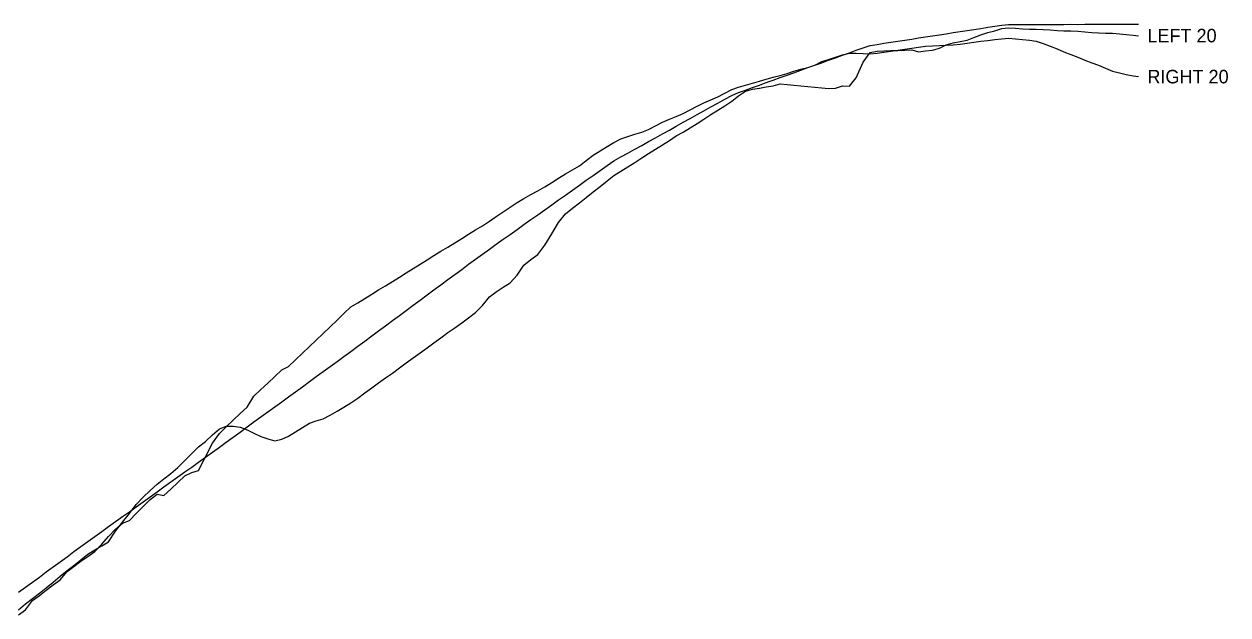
# Model space of a CAD drawing. Extents: x 2005261 to 2010661, y 1001568 to 1006764.
# Drawn here: x 2008591 to 2009460, y 1004765 to 1005191 of the extents above; entities that cross this region are included whole.
import ezdxf

# ---------------------------------------------------------------- set-up
doc = ezdxf.new("R2010")
doc.units = 0
for name, color, linetype in [('RD_DDB_Profile_EX', 7, 'Continuous'), ('RD_Sketch2', 7, 'Continuous'), ('RD_Sketch3', 7, 'Continuous')]:
    doc.layers.add(name, color=color, linetype=linetype)

msp = doc.modelspace()

# ---------------------------------------------------------------- linework, layer by layer
at = {"layer": 'RD_DDB_Profile_EX'}
for points in [[(2009176.73, 1005166.94), (2009181.73, 1005168.71), (2009186.73, 1005170.5), (2009191.73, 1005172.29), (2009196.73, 1005174.08), (2009201.73, 1005175.83), (2009206.73, 1005176.59), (2009211.73, 1005177.35), (2009216.73, 1005178.12), (2009221.73, 1005178.89), (2009226.73, 1005179.66), (2009231.73, 1005180.42), (2009236.73, 1005181.19), (2009241.73, 1005181.96), (2009246.73, 1005182.73), (2009251.73, 1005183.5), (2009256.73, 1005184.26), (2009261.73, 1005185.03), (2009266.73, 1005185.8), (2009271.73, 1005186.57), (2009276.73, 1005187.34), (2009281.73, 1005188.11), (2009286.73, 1005188.87), (2009291.73, 1005189.64), (2009296.73, 1005190.41), (2009301.73, 1005190.94), (2009306.73, 1005190.95), (2009311.73, 1005190.97), (2009316.73, 1005190.98), (2009321.73, 1005191), (2009326.73, 1005190.96), (2009331.73, 1005190.98), (2009336.73, 1005191), (2009341.73, 1005191.02), (2009346.73, 1005191.04), (2009351.73, 1005191.02), (2009356.73, 1005191.04), (2009361.73, 1005191.06), (2009366.73, 1005191.09), (2009371.73, 1005191.11), (2009376.73, 1005191.11), (2009381.73, 1005191.14), (2009386.73, 1005191.17), (2009391.73, 1005191.19), (2009395.62, 1005191.21)], [(2008676.73, 1004846.43), (2008681.73, 1004850.01), (2008686.73, 1004853.59), (2008691.73, 1004857.17), (2008696.73, 1004860.76), (2008701.73, 1004864.34), (2008706.73, 1004867.92), (2008711.73, 1004871.5), (2008716.73, 1004875.08), (2008721.73, 1004878.67), (2008726.73, 1004882.25), (2008731.73, 1004885.83), (2008736.73, 1004889.47), (2008741.73, 1004893.11), (2008746.73, 1004896.75), (2008751.73, 1004900.4), (2008756.73, 1004904.02), (2008761.73, 1004907.66), (2008766.73, 1004911.31), (2008771.73, 1004914.95), (2008776.73, 1004918.59), (2008781.73, 1004922.22), (2008786.73, 1004925.86), (2008791.73, 1004929.5), (2008796.73, 1004933.14), (2008801.73, 1004936.79), (2008806.73, 1004940.42), (2008811.73, 1004944.06), (2008816.73, 1004947.7), (2008821.73, 1004951.35), (2008826.73, 1004955.01), (2008831.73, 1004958.71), (2008836.73, 1004962.41), (2008841.73, 1004966.11), (2008846.73, 1004969.81), (2008851.73, 1004973.5), (2008856.73, 1004977.2), (2008861.73, 1004980.9), (2008866.73, 1004984.6), (2008871.73, 1004988.3), (2008876.73, 1004991.99), (2008881.73, 1004995.69), (2008886.73, 1004999.39), (2008891.73, 1005003.09), (2008896.73, 1005006.79), (2008901.73, 1005010.48), (2008906.73, 1005014.18), (2008911.73, 1005017.88), (2008916.73, 1005021.58), (2008921.73, 1005025.24), (2008926.73, 1005028.79), (2008931.73, 1005032.33), (2008936.73, 1005035.88), (2008941.73, 1005039.42), (2008946.73, 1005042.98), (2008951.73, 1005046.53), (2008956.73, 1005050.07), (2008961.73, 1005053.62), (2008966.73, 1005057.16), (2008971.73, 1005060.72), (2008976.73, 1005064.27), (2008981.73, 1005067.82), (2008986.73, 1005071.36), (2008991.73, 1005074.91), (2008996.73, 1005078.47), (2009001.73, 1005082.01), (2009006.73, 1005085.56), (2009011.73, 1005089.11), (2009016.73, 1005092.53), (2009021.73, 1005095.31), (2009026.73, 1005098.08), (2009031.73, 1005100.86), (2009036.73, 1005103.64), (2009041.73, 1005106.42), (2009046.73, 1005109.19), (2009051.73, 1005111.97), (2009056.73, 1005114.74), (2009061.73, 1005117.52), (2009066.73, 1005120.3), (2009071.73, 1005123.07), (2009076.73, 1005125.85), (2009081.73, 1005128.62), (2009086.73, 1005131.38), (2009091.73, 1005134.15), (2009096.73, 1005136.91), (2009101.73, 1005139.68), (2009106.73, 1005141.79), (2009111.73, 1005143.58), (2009116.73, 1005145.37), (2009121.73, 1005147.16), (2009126.73, 1005148.95), (2009131.73, 1005150.77), (2009136.73, 1005152.56), (2009141.73, 1005154.35), (2009146.73, 1005156.14), (2009151.73, 1005157.93), (2009156.73, 1005159.76), (2009161.73, 1005161.56), (2009166.73, 1005163.35), (2009171.73, 1005165.14), (2009176.73, 1005166.94)], [(2008586.73, 1004781.12), (2008591.73, 1004784.79), (2008596.73, 1004788.46), (2008601.73, 1004792.12), (2008606.73, 1004795.79), (2008611.73, 1004799.45), (2008616.73, 1004803.12), (2008621.73, 1004806.79), (2008626.73, 1004810.45), (2008631.73, 1004814.12), (2008636.73, 1004817.77), (2008641.73, 1004821.35), (2008646.73, 1004824.93), (2008651.73, 1004828.52), (2008656.73, 1004832.1), (2008661.73, 1004835.68), (2008666.73, 1004839.26), (2008671.73, 1004842.85), (2008676.73, 1004846.43)]]:
    msp.add_lwpolyline(points, dxfattribs=at)
at = {"layer": 'RD_Sketch2'}
for points in [[(2009176.73, 1005144.91), (2009181.73, 1005146.75), (2009186.73, 1005146.31), (2009191.73, 1005152.42), (2009196.73, 1005163.73), (2009201.73, 1005170.8), (2009206.73, 1005171.76), (2009211.73, 1005171.92), (2009216.73, 1005172.09), (2009221.73, 1005172.26), (2009226.73, 1005172.43), (2009231.73, 1005172.6), (2009236.73, 1005171.19), (2009241.73, 1005171.82), (2009246.73, 1005172.45), (2009251.73, 1005173.85), (2009256.73, 1005176.14), (2009261.73, 1005177.59), (2009266.73, 1005178.64), (2009271.73, 1005179.69), (2009276.73, 1005181.42), (2009281.73, 1005183.51), (2009286.73, 1005185.02), (2009291.73, 1005186.24), (2009296.73, 1005188.11), (2009301.73, 1005188.53), (2009306.73, 1005188.19), (2009311.73, 1005187.86), (2009316.73, 1005187.6), (2009321.73, 1005187.66), (2009326.73, 1005187.42), (2009331.73, 1005187.05), (2009336.73, 1005186.68), (2009341.73, 1005186.31), (2009346.73, 1005186.3), (2009351.73, 1005186.03), (2009356.73, 1005185.63), (2009361.73, 1005185.22), (2009366.73, 1005184.82), (2009371.73, 1005184.62), (2009376.73, 1005184.63), (2009381.73, 1005184.15), (2009386.73, 1005183.66), (2009391.73, 1005183.18), (2009395.62, 1005182.81)], [(2008676.73, 1004849.84), (2008681.73, 1004854.53), (2008686.73, 1004859.23), (2008691.73, 1004863.07), (2008696.73, 1004866.77), (2008701.73, 1004871.28), (2008706.73, 1004876.21), (2008711.73, 1004881.15), (2008716.73, 1004886.09), (2008721.73, 1004889.97), (2008726.73, 1004894.77), (2008731.73, 1004899.11), (2008736.73, 1004900.95), (2008741.73, 1004901.09), (2008746.73, 1004900.16), (2008751.73, 1004898.35), (2008756.73, 1004895.93), (2008761.73, 1004893.63), (2008766.73, 1004891.74), (2008771.73, 1004890.52), (2008776.73, 1004891.62), (2008781.73, 1004893.83), (2008786.73, 1004896.91), (2008791.73, 1004899.99), (2008796.73, 1004903.06), (2008801.73, 1004904.83), (2008806.73, 1004906.38), (2008811.73, 1004908.89), (2008816.73, 1004911.79), (2008821.73, 1004914.7), (2008826.73, 1004917.82), (2008831.73, 1004921.29), (2008836.73, 1004924.97), (2008841.73, 1004928.65), (2008846.73, 1004932.33), (2008851.73, 1004935.9), (2008856.73, 1004939.36), (2008861.73, 1004943.05), (2008866.73, 1004946.73), (2008871.73, 1004950.41), (2008876.73, 1004953.98), (2008881.73, 1004957.43), (2008886.73, 1004961.12), (2008891.73, 1004964.81), (2008896.73, 1004968.5), (2008901.73, 1004972.06), (2008906.73, 1004975.54), (2008911.73, 1004979.24), (2008916.73, 1004982.93), (2008921.73, 1004987.98), (2008926.73, 1004994.46), (2008931.73, 1004998.02), (2008936.73, 1005001.26), (2008941.73, 1005004.49), (2008946.73, 1005009.9), (2008951.73, 1005017.29), (2008956.73, 1005021.28), (2008961.73, 1005024.99), (2008966.73, 1005031.75), (2008971.73, 1005039.86), (2008976.73, 1005047.96), (2008981.73, 1005054.3), (2008986.73, 1005058.25), (2008991.73, 1005062.19), (2008996.73, 1005066.14), (2009001.73, 1005070.09), (2009006.73, 1005074.03), (2009011.73, 1005077.98), (2009016.73, 1005081.85), (2009021.73, 1005085.03), (2009026.73, 1005088.21), (2009031.73, 1005091.39), (2009036.73, 1005094.57), (2009041.73, 1005097.76), (2009046.73, 1005100.94), (2009051.73, 1005104.12), (2009056.73, 1005107.3), (2009061.73, 1005110.48), (2009066.73, 1005113.23), (2009071.73, 1005116.31), (2009076.73, 1005119.5), (2009081.73, 1005122.7), (2009086.73, 1005125.9), (2009091.73, 1005129.09), (2009096.73, 1005132.29), (2009101.73, 1005135.49), (2009106.73, 1005139.41), (2009111.73, 1005142.86), (2009116.73, 1005144.19), (2009121.73, 1005145.03), (2009126.73, 1005145.87), (2009131.73, 1005146.71), (2009136.73, 1005147.99), (2009141.73, 1005147.53), (2009146.73, 1005147.07), (2009151.73, 1005146.61), (2009156.73, 1005146.14), (2009161.73, 1005145.68), (2009166.73, 1005145.22), (2009171.73, 1005144.76), (2009176.73, 1005144.91)], [(2008586.73, 1004768.38), (2008591.73, 1004772.7), (2008596.73, 1004776.66), (2008601.73, 1004780.48), (2008606.73, 1004784.3), (2008611.73, 1004788.49), (2008616.73, 1004792.79), (2008621.73, 1004796.73), (2008626.73, 1004800.55), (2008631.73, 1004804.64), (2008636.73, 1004808.7), (2008641.73, 1004811.66), (2008646.73, 1004814.62), (2008651.73, 1004817.57), (2008656.73, 1004825.24), (2008661.73, 1004831.66), (2008666.73, 1004838.08), (2008671.73, 1004844.51), (2008676.73, 1004849.84)]]:
    msp.add_lwpolyline(points, dxfattribs=at)
at = {"layer": 'RD_Sketch3'}
for points in [[(2009176.73, 1005167.33), (2009181.73, 1005168.92), (2009186.73, 1005170.27), (2009191.73, 1005170.32), (2009196.73, 1005169.99), (2009201.73, 1005169.66), (2009206.73, 1005170.32), (2009211.73, 1005171), (2009216.73, 1005171.69), (2009221.73, 1005172.37), (2009226.73, 1005173.09), (2009231.73, 1005173.81), (2009236.73, 1005174.53), (2009241.73, 1005175.2), (2009246.73, 1005175.48), (2009251.73, 1005175.76), (2009256.73, 1005176.04), (2009261.73, 1005176.32), (2009266.73, 1005176.66), (2009271.73, 1005177.37), (2009276.73, 1005178.08), (2009281.73, 1005178.79), (2009286.73, 1005179.44), (2009291.73, 1005180.03), (2009296.73, 1005180.63), (2009301.73, 1005181.08), (2009306.73, 1005180.58), (2009311.73, 1005180.08), (2009316.73, 1005179.59), (2009321.73, 1005178.99), (2009326.73, 1005177.08), (2009331.73, 1005175.18), (2009336.73, 1005173.24), (2009341.73, 1005171.24), (2009346.73, 1005169.25), (2009351.73, 1005167.25), (2009356.73, 1005165.26), (2009361.73, 1005163.28), (2009366.73, 1005161.64), (2009371.73, 1005159.48), (2009376.73, 1005157.32), (2009381.73, 1005155.92), (2009386.73, 1005154.85), (2009391.73, 1005153.93), (2009395.62, 1005153.27)], [(2008676.73, 1004843.07), (2008681.73, 1004848.17), (2008686.73, 1004851.96), (2008691.73, 1004850.94), (2008696.73, 1004855.44), (2008701.73, 1004860.24), (2008706.73, 1004865.03), (2008711.73, 1004867.65), (2008716.73, 1004869.06), (2008721.73, 1004878.91), (2008726.73, 1004888.76), (2008731.73, 1004895.6), (2008736.73, 1004900.4), (2008741.73, 1004905.21), (2008746.73, 1004910.02), (2008751.73, 1004914.82), (2008756.73, 1004922.61), (2008761.73, 1004927.35), (2008766.73, 1004932.09), (2008771.73, 1004936.83), (2008776.73, 1004941.57), (2008781.73, 1004944), (2008786.73, 1004948.8), (2008791.73, 1004953.6), (2008796.73, 1004958.39), (2008801.73, 1004963.19), (2008806.73, 1004967.99), (2008811.73, 1004972.78), (2008816.73, 1004977.58), (2008821.73, 1004982.38), (2008826.73, 1004987.01), (2008831.73, 1004990.08), (2008836.73, 1004993.16), (2008841.73, 1004996.23), (2008846.73, 1004999.31), (2008851.73, 1005002.38), (2008856.73, 1005005.46), (2008861.73, 1005008.53), (2008866.73, 1005011.61), (2008871.73, 1005014.68), (2008876.73, 1005018), (2008881.73, 1005021.08), (2008886.73, 1005024.15), (2008891.73, 1005027.23), (2008896.73, 1005030.31), (2008901.73, 1005033.38), (2008906.73, 1005036.46), (2008911.73, 1005039.54), (2008916.73, 1005042.61), (2008921.73, 1005045.69), (2008926.73, 1005049.01), (2008931.73, 1005052.38), (2008936.73, 1005055.76), (2008941.73, 1005059.13), (2008946.73, 1005062.44), (2008951.73, 1005065.28), (2008956.73, 1005068.11), (2008961.73, 1005070.94), (2008966.73, 1005073.78), (2008971.73, 1005076.99), (2008976.73, 1005080.11), (2008981.73, 1005083.05), (2008986.73, 1005085.99), (2008991.73, 1005088.93), (2008996.73, 1005092.71), (2009001.73, 1005096.61), (2009006.73, 1005099.71), (2009011.73, 1005102.81), (2009016.73, 1005105.81), (2009021.73, 1005108.46), (2009026.73, 1005110.05), (2009031.73, 1005111.64), (2009036.73, 1005113.23), (2009041.73, 1005115.2), (2009046.73, 1005117.82), (2009051.73, 1005120.44), (2009056.73, 1005122.62), (2009061.73, 1005124.52), (2009066.73, 1005126.71), (2009071.73, 1005129.31), (2009076.73, 1005131.91), (2009081.73, 1005134.46), (2009086.73, 1005136.52), (2009091.73, 1005138.82), (2009096.73, 1005141.41), (2009101.73, 1005143.88), (2009106.73, 1005145.68), (2009111.73, 1005147.07), (2009116.73, 1005148.52), (2009121.73, 1005149.98), (2009126.73, 1005151.44), (2009131.73, 1005152.85), (2009136.73, 1005154.21), (2009141.73, 1005155.64), (2009146.73, 1005157.12), (2009151.73, 1005158.6), (2009156.73, 1005159.97), (2009161.73, 1005161.46), (2009166.73, 1005164.13), (2009171.73, 1005165.73), (2009176.73, 1005167.33)], [(2008586.73, 1004764.77), (2008591.73, 1004768.46), (2008596.73, 1004775.16), (2008601.73, 1004778.89), (2008606.73, 1004782.63), (2008611.73, 1004786.36), (2008616.73, 1004790.09), (2008621.73, 1004796.06), (2008626.73, 1004799.82), (2008631.73, 1004803.58), (2008636.73, 1004807), (2008641.73, 1004810.61), (2008646.73, 1004815.93), (2008651.73, 1004821.25), (2008656.73, 1004826.57), (2008661.73, 1004831.05), (2008666.73, 1004832.87), (2008671.73, 1004837.97), (2008676.73, 1004843.07)]]:
    msp.add_lwpolyline(points, dxfattribs=at)

# ---------------------------------------------------------------- texts
at = {"layer": 'RD_Sketch2'}
msp.add_text('LEFT 20', height=9.75, dxfattribs=at).set_placement((2009401.96, 1005178.03))
at = {"layer": 'RD_Sketch3'}
msp.add_text('RIGHT 20', height=9.75, dxfattribs=at).set_placement((2009401.96, 1005148.43))

doc.saveas('drawing.dxf')
